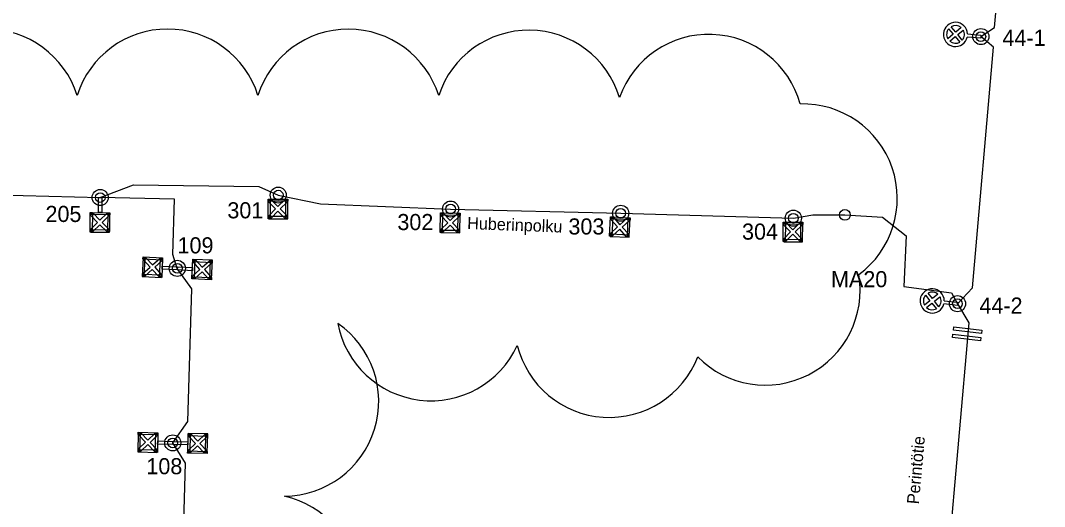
# Model space of a CAD drawing. Extents: x 25497851 to 25498523, y 6686544 to 6687372.
# Drawn here: x 25498083.9 to 25498274.5, y 6687116.4 to 6687207 of the extents above; entities that cross this region are included whole.
import ezdxf

# ---------------------------------------------------------------- set-up
doc = ezdxf.new("R2010")
doc.units = 0
for name, color, linetype in [('KAAPELI', 7, 'Continuous'), ('KEYGWT_ANNOTATION', 7, 'Continuous'), ('MUU_SUUNNITELMAVIIVA', 7, 'Continuous'), ('MUU_UV-SUUNNITELMASYMBOLI', 7, 'Continuous'), ('PYLVAS', 7, 'Continuous'), ('TEKSTI_SUUNNITELMA-ALUE', 7, 'Continuous'), ('VALAISIN', 7, 'Continuous')]:
    doc.layers.add(name, color=color, linetype=linetype)

msp = doc.modelspace()

# ---------------------------------------------------------------- linework, layer by layer
at = {"layer": 'KAAPELI'}
for p, q in [((25498065.63, 6687174.9), (25498098.74, 6687174.02)), ((25498163.96, 6687171.87), (25498195.63, 6687171.09)), ((25498195.63, 6687171.09), (25498227.77, 6687170.17))]:
    msp.add_line(p, q, dxfattribs=at)
for points in [[(25498262.68, 6687204), (25498265.21, 6687205.67), (25498269.02, 6687247.64), (25498266.81, 6687251.15)], [(25498258.33, 6687154.24), (25498261.13, 6687157.19), (25498265.03, 6687202.01), (25498262.68, 6687204)], [(25498098.74, 6687174.02), (25498104.93, 6687176.41), (25498128.27, 6687176.06), (25498131.88, 6687174.47)], [(25498113.09, 6687160.82), (25498112.26, 6687163.39), (25498112.54, 6687173.74), (25498098.74, 6687174.02)], [(25498131.88, 6687174.47), (25498139.73, 6687172.83), (25498163.96, 6687171.87)], [(25498227.77, 6687170.17), (25498231.41, 6687170.82), (25498237.37, 6687170.78)], [(25498237.37, 6687170.78), (25498244.36, 6687170.34), (25498248.8, 6687166.85), (25498248.33, 6687157.43), (25498257.22, 6687156.26), (25498258.33, 6687154.24)], [(25498112.24, 6687128.3), (25498115.07, 6687132.27), (25498115.78, 6687157.03), (25498113.09, 6687160.82)], [(25498258.33, 6687154.24), (25498260.46, 6687150.68), (25498256.59, 6687106.94), (25498254.07, 6687104.33)], [(25498111.22, 6687097.23), (25498113.96, 6687100.34), (25498114.59, 6687124.51), (25498112.24, 6687128.3)]]:
    msp.add_lwpolyline(points, dxfattribs=at)
at = {"layer": 'MUU_SUUNNITELMAVIIVA'}
for centre, radius, start, end in [((25498077.61, 6687187.75), 17.65, 17.5, 162.5), ((25498111.27, 6687187.75), 17.65, 17.5, 162.5), ((25498144.92, 6687187.73), 17.65, 17.4389, 162.4389), ((25498178.53, 6687187.54), 17.65, 16.9283, 161.9283), ((25498212.04, 6687186.77), 17.65, 15.4206, 160.4206), ((25498229.49, 6687173.84), 17.63, 306.4179, 91.4179), ((25498222.55, 6687156.72), 17.65, 224.5747, 9.5747), ((25498132.94, 6687136.05), 17.65, 270.3464, 55.3464), ((25498160.32, 6687153.79), 17.64, 190.5121, 335.5121), ((25498193.52, 6687150.7), 17.65, 193.8467, 338.8467), ((25498129.08, 6687101.2), 17.65, 292.0128, 77.0128)]:
    msp.add_arc(centre, radius, start, end, dxfattribs=at)
at = {"layer": 'MUU_UV-SUUNNITELMASYMBOLI'}
for p, q in [((25498257.57, 6687149.3), (25498257.64, 6687149.9)), ((25498262.78, 6687148.68), (25498257.57, 6687149.3)), ((25498257.64, 6687149.9), (25498262.85, 6687149.28)), ((25498262.85, 6687149.28), (25498262.78, 6687148.68)), ((25498257.41, 6687147.95), (25498257.48, 6687148.55)), ((25498262.62, 6687147.33), (25498257.41, 6687147.95)), ((25498257.48, 6687148.55), (25498262.69, 6687147.93)), ((25498262.69, 6687147.93), (25498262.62, 6687147.33))]:
    msp.add_line(p, q, dxfattribs=at)
msp.add_circle((25498237.37, 6687170.78), 1, dxfattribs=at)
at = {"layer": 'PYLVAS'}
for centre, radius in [((25498262.68, 6687204), 1.5), ((25498262.68, 6687204), 0.9), ((25498098.74, 6687174.02), 1.5), ((25498131.88, 6687174.47), 1.5), ((25498131.88, 6687174.47), 0.9), ((25498098.74, 6687174.02), 0.9), ((25498163.96, 6687171.87), 1.5), ((25498163.96, 6687171.87), 0.9), ((25498195.63, 6687171.09), 1.5), ((25498195.63, 6687171.09), 0.9), ((25498227.77, 6687170.17), 1.5), ((25498227.77, 6687170.17), 0.9), ((25498113.09, 6687160.82), 1.5), ((25498113.09, 6687160.82), 0.9), ((25498258.33, 6687154.24), 1.5), ((25498258.33, 6687154.24), 0.9), ((25498112.24, 6687128.3), 1.5), ((25498112.24, 6687128.3), 0.9)]:
    msp.add_circle(centre, radius, dxfattribs=at)
at = {"layer": 'VALAISIN'}
for p, q in [((25498257.99, 6687204.83), (25498257.14, 6687205.85)), ((25498257.53, 6687204.45), (25498256.52, 6687203.6)), ((25498256.68, 6687205.46), (25498257.53, 6687204.45)), ((25498256.9, 6687203.14), (25498257.92, 6687203.99)), ((25498257.92, 6687203.99), (25498258.77, 6687202.97)), ((25498259.01, 6687205.68), (25498257.99, 6687204.83)), ((25498258.38, 6687204.37), (25498259.39, 6687205.22)), ((25498259.23, 6687203.36), (25498258.38, 6687204.37)), ((25498262.65, 6687203.7), (25498260.15, 6687203.92)), ((25498260.2, 6687204.51), (25498262.7, 6687204.29)), ((25498262.7, 6687204.29), (25498262.65, 6687203.7)), ((25498253.2, 6687154.8), (25498252.17, 6687153.98)), ((25498252.37, 6687155.83), (25498253.2, 6687154.8)), ((25498253.67, 6687155.18), (25498252.84, 6687156.21)), ((25498254.7, 6687156), (25498253.67, 6687155.18)), ((25498254.04, 6687154.71), (25498255.07, 6687155.53)), ((25498254.87, 6687153.67), (25498254.04, 6687154.71)), ((25498255.87, 6687154.8), (25498258.36, 6687154.53)), ((25498258.36, 6687154.53), (25498258.3, 6687153.93)), ((25498252.54, 6687153.51), (25498253.57, 6687154.33)), ((25498253.57, 6687154.33), (25498254.4, 6687153.3)), ((25498258.3, 6687153.93), (25498255.8, 6687154.21))]:
    msp.add_line(p, q, dxfattribs=at)
for points in [[(25498099.04, 6687174.02), (25498099.01, 6687171.21), (25498098.41, 6687171.21), (25498098.44, 6687174.03)], [(25498130.39, 6687173.72), (25498130.39, 6687170.07), (25498129.99, 6687170.07), (25498129.99, 6687173.72)], [(25498133.64, 6687173.72), (25498133.64, 6687173.32), (25498130.12, 6687173.32), (25498130.12, 6687173.72)], [(25498130.54, 6687173.6), (25498131.82, 6687172.32), (25498133.1, 6687173.6), (25498133.52, 6687173.6), (25498133.52, 6687173.17), (25498132.24, 6687171.9), (25498133.52, 6687170.62), (25498133.52, 6687170.2), (25498133.1, 6687170.2), (25498131.82, 6687171.47), (25498130.54, 6687170.2), (25498130.12, 6687170.2), (25498130.12, 6687170.62), (25498131.39, 6687171.9), (25498130.12, 6687173.17), (25498130.12, 6687173.6)], [(25498133.64, 6687170.2), (25498133.64, 6687173.6), (25498133.24, 6687173.6), (25498133.24, 6687170.2)], [(25498097.29, 6687171.23), (25498097.24, 6687167.58), (25498096.84, 6687167.58), (25498096.89, 6687171.23)], [(25498097.43, 6687171.1), (25498098.69, 6687169.81), (25498099.99, 6687171.07), (25498100.41, 6687171.07), (25498100.41, 6687170.65), (25498099.11, 6687169.38), (25498100.38, 6687168.09), (25498100.37, 6687167.67), (25498099.95, 6687167.67), (25498098.68, 6687168.96), (25498097.39, 6687167.7), (25498096.97, 6687167.71), (25498096.97, 6687168.13), (25498098.26, 6687169.39), (25498097, 6687170.68), (25498097, 6687171.11)], [(25498100.53, 6687171.19), (25498100.53, 6687170.79), (25498097, 6687170.83), (25498097.01, 6687171.23)], [(25498100.5, 6687167.67), (25498100.53, 6687171.07), (25498100.13, 6687171.07), (25498100.1, 6687167.67)], [(25498130.12, 6687170.47), (25498130.12, 6687170.07), (25498133.64, 6687170.07), (25498133.64, 6687170.47)], [(25498162.48, 6687171.14), (25498162.42, 6687167.5), (25498162.02, 6687167.5), (25498162.08, 6687171.15)], [(25498162.62, 6687171.02), (25498163.88, 6687169.72), (25498165.18, 6687170.98), (25498165.6, 6687170.97), (25498165.6, 6687170.55), (25498164.3, 6687169.29), (25498165.56, 6687168), (25498165.55, 6687167.57), (25498165.13, 6687167.58), (25498163.87, 6687168.88), (25498162.57, 6687167.62), (25498162.14, 6687167.63), (25498162.15, 6687168.05), (25498163.45, 6687169.31), (25498162.19, 6687170.6), (25498162.2, 6687171.03)], [(25498165.73, 6687171.09), (25498165.72, 6687170.69), (25498162.19, 6687170.75), (25498162.2, 6687171.15)], [(25498165.67, 6687167.57), (25498165.72, 6687170.97), (25498165.32, 6687170.98), (25498165.27, 6687167.58)], [(25498194.14, 6687170.41), (25498193.97, 6687166.77), (25498193.57, 6687166.79), (25498193.74, 6687170.43)], [(25498194.28, 6687170.28), (25498195.5, 6687168.95), (25498196.84, 6687170.16), (25498197.26, 6687170.14), (25498197.24, 6687169.72), (25498195.9, 6687168.5), (25498197.12, 6687167.17), (25498197.1, 6687166.74), (25498196.67, 6687166.76), (25498195.46, 6687168.1), (25498194.12, 6687166.89), (25498193.69, 6687166.91), (25498193.71, 6687167.33), (25498195.05, 6687168.54), (25498193.84, 6687169.88), (25498193.86, 6687170.3)], [(25498197.39, 6687170.26), (25498197.37, 6687169.86), (25498193.84, 6687170.03), (25498193.86, 6687170.43)], [(25498197.22, 6687166.74), (25498197.38, 6687170.13), (25498196.98, 6687170.15), (25498196.82, 6687166.76)], [(25498096.97, 6687167.98), (25498096.97, 6687167.58), (25498100.49, 6687167.54), (25498100.5, 6687167.94)], [(25498162.15, 6687167.9), (25498162.14, 6687167.5), (25498165.67, 6687167.45), (25498165.68, 6687167.85)], [(25498226.29, 6687169.44), (25498226.25, 6687165.79), (25498225.85, 6687165.8), (25498225.89, 6687169.44)], [(25498226.43, 6687169.31), (25498227.7, 6687168.02), (25498228.99, 6687169.29), (25498229.41, 6687169.28), (25498229.41, 6687168.86), (25498228.12, 6687167.6), (25498229.38, 6687166.31), (25498229.38, 6687165.88), (25498228.95, 6687165.89), (25498227.69, 6687167.18), (25498226.4, 6687165.91), (25498225.97, 6687165.92), (25498225.98, 6687166.34), (25498227.27, 6687167.6), (25498226, 6687168.89), (25498226.01, 6687169.32)], [(25498229.54, 6687169.4), (25498229.53, 6687169), (25498226, 6687169.04), (25498226.01, 6687169.44)], [(25498229.5, 6687165.88), (25498229.53, 6687169.28), (25498229.13, 6687169.29), (25498229.1, 6687165.89)], [(25498193.71, 6687167.18), (25498193.69, 6687166.78), (25498197.21, 6687166.61), (25498197.23, 6687167.01)], [(25498225.97, 6687166.19), (25498225.97, 6687165.79), (25498229.5, 6687165.76), (25498229.5, 6687166.16)], [(25498107.11, 6687162.8), (25498106.71, 6687162.82), (25498106.55, 6687159.3), (25498106.95, 6687159.28)], [(25498110.21, 6687162.23), (25498108.88, 6687161.02), (25498110.09, 6687159.68), (25498110.07, 6687159.26), (25498109.65, 6687159.28), (25498108.44, 6687160.61), (25498107.1, 6687159.4), (25498106.68, 6687159.42), (25498106.7, 6687159.84), (25498108.03, 6687161.06), (25498106.82, 6687162.39), (25498106.84, 6687162.82), (25498107.26, 6687162.8), (25498108.48, 6687161.46), (25498109.81, 6687162.68), (25498110.23, 6687162.66)], [(25498110.34, 6687162.37), (25498106.7, 6687162.54), (25498106.72, 6687162.94), (25498110.36, 6687162.77)], [(25498110.19, 6687159.13), (25498109.79, 6687159.15), (25498109.96, 6687162.67), (25498110.36, 6687162.65)], [(25498115.99, 6687162.51), (25498116.38, 6687162.49), (25498116.22, 6687158.96), (25498115.82, 6687158.98)], [(25498115.96, 6687159.4), (25498117.3, 6687160.62), (25498116.08, 6687161.95), (25498116.1, 6687162.38), (25498116.53, 6687162.36), (25498117.74, 6687161.02), (25498119.08, 6687162.24), (25498119.5, 6687162.22), (25498119.48, 6687161.79), (25498118.14, 6687160.58), (25498119.36, 6687159.24), (25498119.34, 6687158.82), (25498118.92, 6687158.84), (25498117.7, 6687160.17), (25498116.37, 6687158.96), (25498115.94, 6687158.98)], [(25498119.51, 6687162.34), (25498116.11, 6687162.5), (25498116.09, 6687162.1), (25498119.49, 6687161.94)], [(25498119.06, 6687158.83), (25498119.46, 6687158.81), (25498119.63, 6687162.33), (25498119.23, 6687162.35)], [(25498113.07, 6687160.52), (25498110.26, 6687160.65), (25498110.29, 6687161.25), (25498113.1, 6687161.12)], [(25498113.1, 6687161.12), (25498115.91, 6687160.98), (25498115.89, 6687160.39), (25498113.07, 6687160.52)], [(25498106.67, 6687159.29), (25498110.07, 6687159.13), (25498110.09, 6687159.53), (25498106.69, 6687159.69)], [(25498115.83, 6687159.26), (25498119.47, 6687159.09), (25498119.46, 6687158.69), (25498115.81, 6687158.86)], [(25498106.23, 6687130.15), (25498105.83, 6687130.16), (25498105.74, 6687126.63), (25498106.14, 6687126.62)], [(25498109.46, 6687129.79), (25498105.82, 6687129.88), (25498105.83, 6687130.28), (25498109.47, 6687130.19)], [(25498109.34, 6687129.65), (25498108.03, 6687128.4), (25498109.28, 6687127.09), (25498109.27, 6687126.67), (25498108.84, 6687126.68), (25498107.6, 6687127.99), (25498106.29, 6687126.74), (25498105.87, 6687126.75), (25498105.88, 6687127.17), (25498107.18, 6687128.42), (25498105.94, 6687129.73), (25498105.95, 6687130.15), (25498106.37, 6687130.14), (25498107.62, 6687128.84), (25498108.92, 6687130.08), (25498109.35, 6687130.07)], [(25498109.39, 6687126.54), (25498108.99, 6687126.55), (25498109.07, 6687130.08), (25498109.47, 6687130.07)], [(25498115.1, 6687130.05), (25498115.5, 6687130.04), (25498115.41, 6687126.51), (25498115.02, 6687126.52)], [(25498115.15, 6687126.94), (25498116.46, 6687128.19), (25498115.21, 6687129.5), (25498115.22, 6687129.92), (25498115.64, 6687129.91), (25498116.89, 6687128.6), (25498118.2, 6687129.85), (25498118.62, 6687129.84), (25498118.61, 6687129.42), (25498117.3, 6687128.17), (25498118.55, 6687126.86), (25498118.54, 6687126.44), (25498118.11, 6687126.45), (25498116.87, 6687127.76), (25498115.56, 6687126.51), (25498115.14, 6687126.52)], [(25498118.62, 6687129.96), (25498115.22, 6687130.05), (25498115.21, 6687129.65), (25498118.61, 6687129.56)], [(25498118.26, 6687126.44), (25498118.66, 6687126.43), (25498118.75, 6687129.96), (25498118.35, 6687129.97)], [(25498112.24, 6687128), (25498109.42, 6687128.06), (25498109.44, 6687128.66), (25498112.25, 6687128.59)], [(25498112.25, 6687128.59), (25498115.06, 6687128.53), (25498115.05, 6687127.93), (25498112.24, 6687128)], [(25498105.86, 6687126.63), (25498109.26, 6687126.54), (25498109.27, 6687126.94), (25498105.87, 6687127.03)], [(25498115.02, 6687126.8), (25498118.67, 6687126.71), (25498118.66, 6687126.31), (25498115.01, 6687126.4)]]:
    msp.add_lwpolyline(points, close=True, dxfattribs=at)
for centre, radius, start, end in [((25498257.96, 6687204.41), 2.25, 2.6413, 174.979), ((25498257.96, 6687204.41), 1.65, 50.4547, 119.5033), ((25498257.96, 6687204.41), 2.25, 174.979, 347.3167), ((25498257.96, 6687204.41), 1.65, 140.4547, 174.979), ((25498257.96, 6687204.41), 1.65, 174.979, 209.5033), ((25498257.96, 6687204.41), 1.65, 320.4547, 354.979), ((25498257.96, 6687204.41), 1.65, 354.979, 29.5033), ((25498257.96, 6687204.41), 1.65, 230.4547, 299.5033), ((25498253.62, 6687154.75), 2.25, 1.2856, 173.6233), ((25498253.62, 6687154.75), 1.65, 49.099, 118.1477), ((25498253.62, 6687154.75), 2.25, 173.6233, 345.9611), ((25498253.62, 6687154.75), 1.65, 173.6233, 208.1477), ((25498253.62, 6687154.75), 1.65, 139.099, 173.6233), ((25498253.62, 6687154.75), 1.65, 319.099, 353.6233), ((25498253.62, 6687154.75), 1.65, 353.6233, 28.1477), ((25498253.62, 6687154.75), 1.65, 229.099, 298.1477)]:
    msp.add_arc(centre, radius, start, end, dxfattribs=at)

# ---------------------------------------------------------------- texts
at = {"layer": 'KEYGWT_ANNOTATION'}
for s, p in [('44-1', (25498266.7, 6687202.28)), ('MA20', (25498234.78, 6687157.31)), ('44-2', (25498262.41, 6687152.39))]:
    msp.add_text(s, height=3, dxfattribs=at).set_placement(p)
at = {"layer": 'TEKSTI_SUUNNITELMA-ALUE'}
for s, p in [('205', (25498088.55, 6687169.46)), ('301', (25498122.41, 6687170.14)), ('302', (25498154.06, 6687167.95)), ('303', (25498185.9, 6687167.13)), ('304', (25498218.22, 6687166.17)), ('109', (25498113.13, 6687163.61)), ('108', (25498107.33, 6687122.46))]:
    msp.add_text(s, height=3, dxfattribs=at).set_placement(p)
for s, rotation, p in [('Huberinpolku', 357.849, (25498167.02, 6687168.15)), ('Perintötie', 84.8782, (25498251.14, 6687116.81))]:
    msp.add_text(s, height=2.25, rotation=rotation, dxfattribs=at).set_placement(p)

doc.saveas('drawing.dxf')
